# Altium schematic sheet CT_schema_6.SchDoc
size 252 x 159 mm
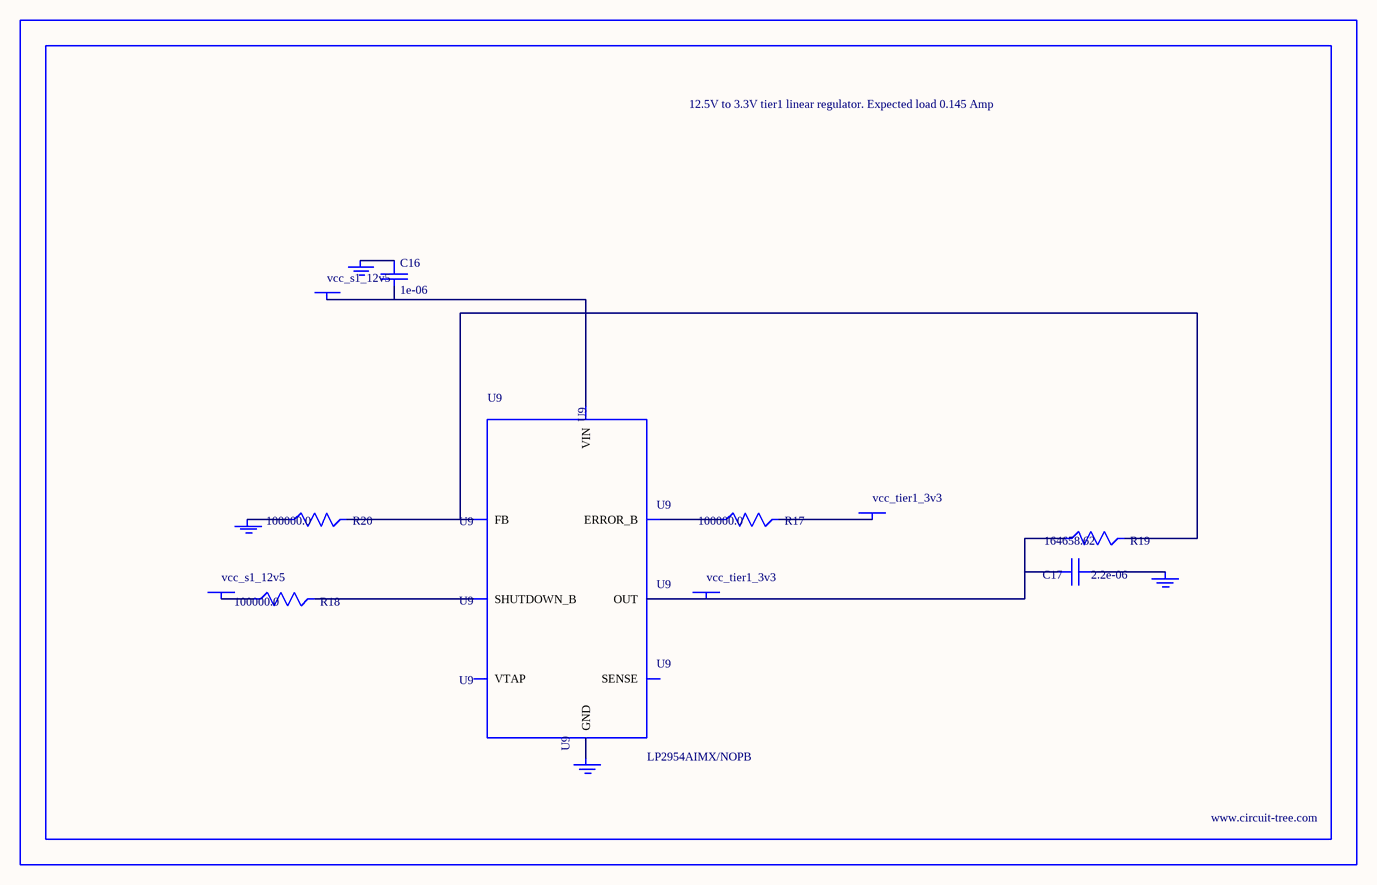
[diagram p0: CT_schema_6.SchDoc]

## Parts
BORDER5  (no value)
C16  1e-06  [EXV-9B]
C17  2.2e-06  [EXV-9B]
GND_INSTANCE_5_0  (no value)
GND_INSTANCE_5_1  (no value)
GND_INSTANCE_5_2  (no value)
GND_INSTANCE_5_3  (no value)
POWER_INSTANCE_5_0  vcc_s1_12v5
POWER_INSTANCE_5_1  vcc_tier1_3v3
POWER_INSTANCE_5_2  vcc_s1_12v5
POWER_INSTANCE_5_3  vcc_tier1_3v3
R17  100000.0  [R0603]
R18  100000.0  [R0603]
R19  164658.62  [R0603]
R20  100000.0  [R0603]
U9  LP2954AIMX/NOPB  [LP2954]

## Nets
NetC16_1: C16.1 GND_INSTANCE_5_2.0(GND)
NetC16_2: C16.2 POWER_INSTANCE_5_2.0(PWR) U9.8(VIN)
NetC17_1: C17.1 GND_INSTANCE_5_0.0(GND)
NetC17_2: C17.2 POWER_INSTANCE_5_3.0(PWR) R19.1 U9.1(OUT)
NetGND_INSTANCE_5_1_0: GND_INSTANCE_5_1.0(GND) R20.1
NetGND_INSTANCE_5_3_0: GND_INSTANCE_5_3.0(GND) U9.4(GND)
NetPOWER_INSTANCE_5_0_0: POWER_INSTANCE_5_0.0(PWR) R18.1
NetPOWER_INSTANCE_5_1_0: POWER_INSTANCE_5_1.0(PWR) R17.2
NetR17_1: R17.1 U9.5(ERROR_B)
NetR18_2: R18.2 U9.3(SHUTDOWN_B)
NetR19_2: R19.2 R20.2 U9.7(FB)

Not connected (* = marked no-connect by the designer): U9 2(SENSE) 6(VTAP)

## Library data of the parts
BORDER5 = BORDER_PAGE5
C16 = EDK105M050A9BAA
C17 = EDK225M050A9BAA
GND_INSTANCE_5_0-GND_INSTANCE_5_3 = GND
POWER_INSTANCE_5_0-POWER_INSTANCE_5_3 = PWR
R17 R18 R20 = RC0603JR-07100KL
R19 = R19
